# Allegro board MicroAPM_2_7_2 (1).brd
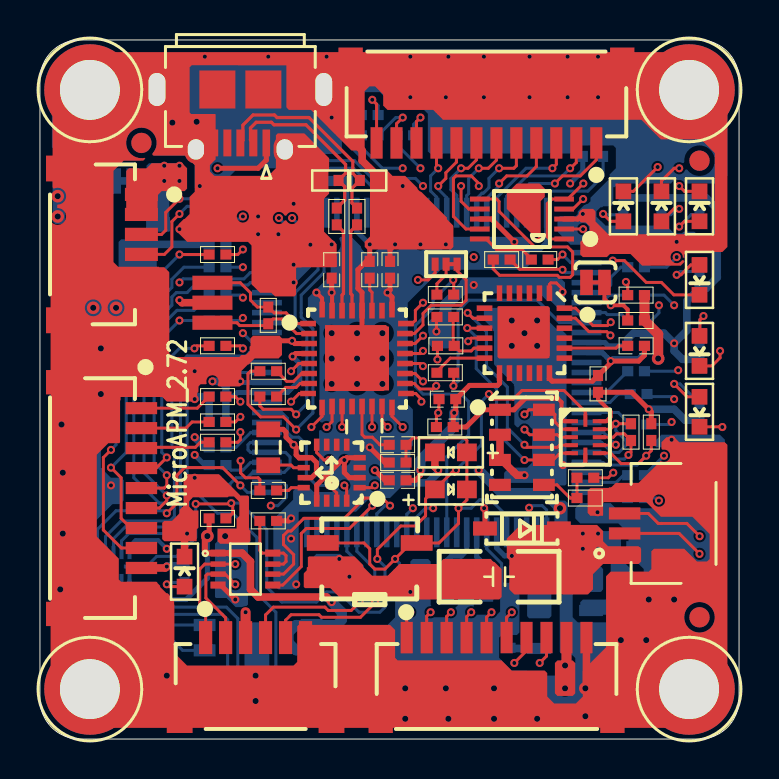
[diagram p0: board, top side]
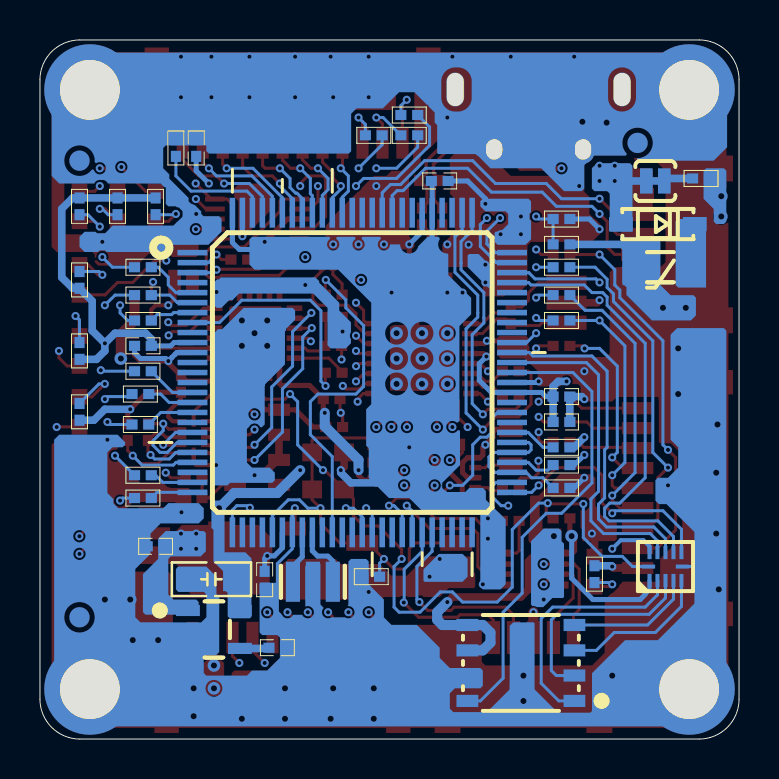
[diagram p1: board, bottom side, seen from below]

Outline 35 x 35 mm; copper layers: TOP, ART02, ART03, BOTTOM. Coordinates in mm from the lower left corner of the outline.
Outline path: 0,33 0,2 arc(0.59,0.59) 2,0 33,0 arc(34.41,0.59) 35,2 35,33 arc(34.41,34.41) 33,35 2,35 arc(0.59,34.41) 0,33

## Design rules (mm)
net group 3.3V: nets 3.3V SPI_OE
net group $$$14: nets $$$14 PH3
net group $$$15: nets $$$15 PE5
net group $$$16: nets $$$16 PE4
net group $$$17: nets $$$17 PE3
net group $$$19: nets $$$19 PH4
net group $$$20: nets $$$20 PH5
net group $$$21: nets $$$21 PB5
net group $$$22: nets $$$22 PB6
net group $$$23: nets $$$23 IN6
net group $$$24: nets $$$24 IN5
net group $$$25: nets $$$25 PPM_MISO
net group $$$26: nets $$$26 PPM_MOSI
net group $$$27: nets $$$27 PPM_SCK
net group $$$4718: nets $$$4718 PL1
net group $$$21225: nets $$$21225 PE1
net group $$$21228: nets $$$21228 PE0
net group $$$23578: nets $$$23578 PJ3
net group $$$25859: nets $$$25859 IN7
net group $$$25863: nets $$$25863 IN0
net group $$$27159: nets $$$27159 $$$27864
net group $$$27161: nets $$$27161 $$$27865
net group $$$27480: nets $$$27480 $$$27485
net group CH5: nets CH5 IN4
net group CS_MS5611: nets CS_MS5611 PG1
net group INT: nets INT PE6
net group PA1: nets PA1 PPM_PD0
net group PA2: nets PA2 PPM_PD1

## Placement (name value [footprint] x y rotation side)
C1  CAP0402-CAP  [C0402]  20.27 15.62 0 top
C2  CAP0402-CAP  [C0402]  8.89 15.88 180 bottom
C3  CAP0402-CAP  [C0402]  29.84 19.68 0 bottom
C4  CAP0402-CAP  [C0402]  17.91 12.95 180 top
C5  CAP0402-CAP  [C0402]  27.94 17.78 270 top
C6  CAP0402-CAP  [C0402]  14.99 27.94 180 bottom
C7  CAP0402-CAP  [C0402]  27.18 29.59 270 bottom
C8  CAP0402-CAP  [C0402]  11.43 12.45 0 top
C9  CAP0402-CAP  [C0402]  20.4 17.02 0 top
C10  CAP0805  [0805]  11.43 14.61 90 top
C11  CAP0402-CAP  [C0402]  23.11 4.57 0 bottom
C12  CAP1206  [C1206]  22.99 8.13 180 top
C13  CAP0402-CAP  [C0402]  29.84 19.68 180 top
C14  CAP0402-CAP  [C0402]  17.53 23.5 90 top
C15  CAP0402-CAP  [C0402]  17.91 14.73 0 top
C16  CAP0402-CAP  [C0402]  14.61 23.5 90 top
C17  CAP0402-CAP  [C0402]  16.51 23.5 90 top
C18  CAP0402-CAP  [C0402]  23.75 7.98 270 bottom
C19  CAP0402-CAP  [C0402]  8.89 17.14 180 bottom
C21  CAP0402-CAP  [C0402]  29.21 9.65 180 bottom
C22  CAP0805  [C0805]  26.42 8 270 bottom
D1  DIODESOD-123  [SOD-123]  4.06 25.78 0 bottom
D2  DIODE  [DIO-0603]  20.57 12.5 0 top
D3  DIODE  [DIO-0603]  20.57 14.35 180 top
D4  DIODESOD-123  [SOD-123]  24.13 10.54 180 top
F2  PTCSMD  [PTC-1206]  3.94 23.62 0 bottom
IC2  AT45DB161D-MU-NOPAD  [VDFN-8-NO-BOTTOM-PAD]  10.92 3.81 0 bottom
J1  CON6-SMD  [SD-53621-06]  5.08 24.77 270 top
J2  CON6-SMD  [SD-53621-06]  10.79 5.08 0 top
J3  CON4-SMD  [SD-53621-04]  33.15 10.79 90 top
J4  CON10-SMD  [SD-53621-10]  5.08 12.06 270 top
J5  CON10-SMD  [SD-53621-10]  22.86 5.08 0 top
J6  CON12-SMD  [SD-53621-12]  22.35 29.84 180 top
J18  MICRO_USB  [MOLEX_MICRO_USB_AB_BOTTOM_MOUNT]  10.03 29.84 0 top
LED1  LED  [LED-0603]  31.11 26.67 0 top
LED2  LED  [LED-0603]  29.21 26.67 0 top
LED3  LED  [LED-0603]  33.02 26.67 0 top
LED4  LED  [LED-0603]  33.02 16.38 180 top
LED5  LED  [LED-0603]  33.02 19.43 180 top
LED6  LED  [LED-0603]  7.24 8.38 0 top
LED7  LED  [LED-0603]  33.02 22.99 180 top
NOREF  #VAL  [unnamed]  33.02 6.1 0 top
NOREF#2  #VAL  [unnamed]  33.02 28.96 0 top
NOREF#3  -  [#2]  2 0 90 top
NOREF#4  -  [#2]  2.5 2.5 90 top
NOREF#5  #VAL  [unnamed]  32.5 2.5 0 top
NOREF#6  #VAL  [unnamed]  2.5 2.5 0 top
NOREF#7  -  [#2]  0 33.03 0 top
NOREF#8  -  [#2]  20.89 25.85 0 top
NOREF#9  #VAL  [unnamed]  2.5 32.5 0 top
NOREF#10  #VAL  [unnamed]  5.08 29.84 0 top
NOREF#11  -  [#2]  -99.11 -34.19 0 top
NOREF#12  #VAL  [unnamed]  32.5 32.5 0 top
NOREF#13  -  [#2]  2.5 32.5 0 top
NOREF#14  #VAL  [unnamed]  33.02 28.96 180 bottom
NOREF#15  #VAL  [unnamed]  33.02 6.1 180 bottom
NOREF#16  #VAL  [unnamed]  5.08 29.84 180 bottom
R1  RESISTOR0402-RES_2  [R0402]  29.84 23.62 180 bottom
R2  RESISTOR0402-RES_2  [R0402]  29.84 22.23 180 bottom
R3  RESISTOR0402-RES_2  [R0402]  29.84 20.95 180 bottom
R4  RESISTOR0402-RES_2  [R0402]  29.84 18.41 180 bottom
R5  RESISTOR0402-RES_2  [R0402]  29.97 17.27 180 bottom
R6  RESISTOR0402-RES_2  [R0402]  29.97 15.75 180 bottom
R7  RESISTOR0402-RES_2  [R0402]  29.84 13.21 180 bottom
R8  RESISTOR0402-RES_2  [R0402]  29.84 12.06 180 bottom
R9  RESISTOR0402-RES  [R0402]  29.84 22.23 0 top
R10  RESISTOR0402-RES_2  [R0402]  27.3 13.08 0 top
R11  RESISTOR0402-RES_2  [R0402]  20.29 22.25 180 top
R12  RESISTOR0402-RES  [R0402]  11.43 10.92 0 top
R13  RESISTOR0402-RES  [R0402]  31.11 26.67 90 bottom
R14  RESISTOR0402-RES_2  [R0402]  8.89 13.72 0 bottom
R15  RESISTOR0402-RES_2  [R0402]  8.89 12.57 0 bottom
R16  RESISTOR0402-RES  [R0402]  29.84 20.95 0 top
R17  RES  [R0402]  30.61 15.37 90 top
R18  RESISTOR0402-RES  [R0402]  29.21 26.67 90 bottom
R19  RESISTOR0402-RES_2  [R0402]  20.29 18.34 0 top
R20  RESISTOR0402-RES  [R0402]  33.02 26.67 90 bottom
R21  RES  [R0402]  29.59 15.37 270 top
R22  RESISTOR0402-RES_2  [R0402]  20.32 19.68 180 top
R23  RESISTOR0402-RES_2  [R0402]  20.29 21.13 180 top
R24  RES  [R0402]  18.41 8.13 0 bottom
R25  RESISTOR0402-RES_2  [R0402]  8.89 11.05 0 top
R26  RESISTOR0402-RES  [R0402]  17.91 13.84 180 top
R27  RESISTOR0402-RES_2  [R0402]  23.11 24 180 top
R28  RESISTOR0402-RES  [R0402]  28.19 29.59 270 bottom
R29  RESISTOR0402-RES_2  [R0402]  11.43 21.21 90 top
R30  RESISTOR0402-RES_2  [R0402]  25.02 24 180 top
R31  RESISTOR0402-RES_2  [R0402]  14.86 26.16 90 top
R32  RESISTOR0402-RES_2  [R0402]  33.02 16.38 90 bottom
R33  RESISTOR0402-RES_2  [R0402]  27.3 12.06 0 top
R34  RESISTOR0402-RES_2  [R0402]  15.88 26.16 90 top
R35  RESISTOR0402-RES_2  [R0402]  33.02 19.43 90 bottom
R36  RESISTOR0402-RES  [R0402]  7.24 8.26 90 bottom
R37  RESISTOR0402-RES  [R0402]  8.89 24.77 180 bottom
R38  RESISTOR0402-RES_2  [R0402]  8.89 24.26 0 top
R39  RESISTOR0402-RES_2  [R0402]  8.89 23.62 0 bottom
R40  RESISTOR0402-RES_2  [R0402]  8.89 22.23 0 bottom
R41  RESISTOR0402-RES_2  [R0402]  8.89 20.95 0 bottom
R42  RESISTOR0402-RES_2  [R0402]  8.89 19.68 0 top
R43  RESISTOR0402-RES_2  [R0402]  8.89 14.86 0 top
R44  RESISTOR0402-RES_2  [R0402]  8.89 15.88 0 top
R45  RESISTOR0402-RES_2  [R0402]  8.89 17.14 0 top
R46  RESISTOR0402-RES_2  [R0402]  11.43 17.14 0 top
R47  RESISTOR0402-RES_2  [R0402]  11.43 18.41 0 top
R48  RESISTOR0402-RES  [R0402]  8.89 14.61 180 bottom
R49  RESISTOR0402-RES_2  [R0402]  1.91 28.07 180 bottom
R50  RESISTOR0402-RES_2  [R0402]  18.29 30.23 180 bottom
R51  RESISTOR0402-RES_2  [R0402]  33.02 22.99 90 bottom
R52  RESISTOR0402-RES_2  [R0402]  16.51 30.23 180 bottom
R53  RESISTOR0402-RES_2  [R0402]  16.51 31.24 180 bottom
R54  RES  [R0402]  8.89 26.04 180 bottom
SJ1  SOLDERJUMPERNO  [SJ_2S-NO]  4.19 27.94 180 bottom
SJ4  JUMP3P  [JUMP3]  20.33 23.77 0 top
SJ10  SOLDERJUMPERNO  [SJ_2S-NO]  27.81 22.86 0 top
SW1  PTS044  [PTS-044]  16.51 9.02 180 top
U1  ATMEGA1280-16AU  [TQFP100]  19.37 18.35 180 bottom
U2  PCA9306DC  [VSSOP8]  10.29 8.51 0 top
U3  V_REG_LDOSMD  [SOT23-5]  26.29 5.49 270 bottom
U5  MPU-3000  [QFN-24]  24.26 20.32 270 top
U7  TS5A23157  [MSOP10]  24.13 26.04 90 top
U8  ATMEGA32U2-MU  [ATMEL_QFN32]  15.88 19.05 0 top
U12  -  [MS5611-01BA]  24.13 14.61 0 top
U13  HMC5883L  [LPCC16]  14.61 13.34 180 top
U_14  TXB0104UQFN  [UQFN-12]  27.3 15.11 270 top
U_15  TXB0104UQFN  [UQFN-12]  3.68 8.64 180 bottom
Y1  CSTCT16M0V53  [RESONATOR]  8.64 21.84 270 top
Y2  CSTCT16M0V53  [RESONATOR]  21.34 7.87 0 bottom
Z1  VARISTORCN0603  [FB-0402]  16.43 27.97 0 top
Z2  VARISTORCN0603  [FB-0402]  14.53 27.97 180 top

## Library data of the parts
C1-C9 C11 C13-C19 C21 = C0402: Tolerance: #TOL; User Part Number: HAMP
C10 = 0805: Tolerance: #TOL; User Part Number: HAMP
C12 = C1206: Tolerance: #TOL; User Part Number: HAMP
C22 = C0805: Tolerance: #TOL; User Part Number: HAMP
D1 D4 = SOD-123: Tolerance: #TOL; User Part Number: HAMP
D2 D3 = DIO-0603: Tolerance: #TOL; User Part Number: HAMP
F2 = PTC-1206: Tolerance: #TOL; User Part Number: HAMP
IC2 = VDFN-8-NO-BOTTOM-PAD: Tolerance: #TOL; User Part Number: HAMP
J1 J2 = SD-53621-06: Tolerance: #TOL; User Part Number: HAMP
J3 = SD-53621-04: Tolerance: #TOL; User Part Number: HAMP
J4 J5 = SD-53621-10: Tolerance: #TOL; User Part Number: HAMP
J6 = SD-53621-12: Tolerance: #TOL; User Part Number: HAMP
J18 = MOLEX_MICRO_USB_AB_BOTTOM_MOUNT: Tolerance: #TOL; User Part Number: HAMP
LED1-LED7 = LED-0603: Tolerance: #TOL; User Part Number: HAMP
NOREF NOREF#2 NOREF#5 NOREF#6 NOREF#9 NOREF#10 NOREF#12 NOREF#14-NOREF#16 = -: Tolerance: #TOL; User Part Number: HAMP
R1-R8 R10 R11 R14 R15 R19 R22 R23 R25 R27 R29-R35 R38-R47 R51 = R0402: Tolerance: #TOL; User Part Number: HAMP; signal model: R0402_RESISTOR0402-RES_2
R9 R12 R13 R16-R18 R20 R21 R24 R26 R28 R36 R37 R48-R50 R52-R54 = R0402: Tolerance: #TOL; User Part Number: HAMP
SJ1 SJ10 = SJ_2S-NO: Tolerance: #TOL; User Part Number: HAMP
SJ4 = JUMP3: Tolerance: #TOL; User Part Number: HAMP
SW1 = PTS-044: Tolerance: #TOL; User Part Number: HAMP
U1 = TQFP100: Tolerance: #TOL; User Part Number: HAMP
U2 = VSSOP8: Tolerance: #TOL; User Part Number: HAMP
U3 = SOT23-5: Tolerance: #TOL; User Part Number: HAMP
U5 = QFN-24: Tolerance: #TOL; User Part Number: HAMP
U7 = MSOP10: Tolerance: #TOL; User Part Number: HAMP
U8 = ATMEL_QFN32: Tolerance: #TOL; User Part Number: HAMP
U12 = MS5611-01BA: Tolerance: #TOL; User Part Number: HAMP
U13 = LPCC16: Tolerance: #TOL; User Part Number: HAMP
U_14 U_15 = UQFN-12: Tolerance: #TOL; User Part Number: HAMP
Y1 Y2 = RESONATOR: Tolerance: #TOL; User Part Number: HAMP
Z1 Z2 = FB-0402: Tolerance: #TOL; User Part Number: HAMP

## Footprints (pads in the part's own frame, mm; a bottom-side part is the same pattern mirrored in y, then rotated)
0805
  rect 0.787x1.194 smd: 1(-0.9,0) 2(0.9,0)
ATMEL_QFN32
  rect 0.787x0.279 smd: 1(-2.45,1.75) 2(-2.4,1.25) 3(-2.4,0.75) 4(-2.4,0.25) 5(-2.4,-0.25) 6(-2.4,-0.75) 7(-2.4,-1.25) 8(-2.45,-1.75) 17(2.45,-1.75) 18(2.4,-1.25) 19(2.4,-0.75) 20(2.4,-0.25) 21(2.4,0.25) 22(2.4,0.75) 23(2.4,1.25) 24(2.45,1.75)
  rect 0.279x0.787 smd: 9(-1.75,-2.45) 10(-1.25,-2.4) 11(-0.75,-2.4) 12(-0.25,-2.4) 13(0.25,-2.4) 14(0.75,-2.4) 15(1.25,-2.4) 16(1.75,-2.45) 25(1.75,2.45) 26(1.25,2.4) 27(0.75,2.4) 28(0.25,2.4) 29(-0.25,2.4) 30(-0.75,2.4) 31(-1.25,2.4) 32(-1.75,2.45)
  rect 3.2x3.2 smd: 33(0,0)
C0402
  rect 0.559x0.508 smd: 1(-0.42,0) 2(0.42,0)
C0805
  rect 1.194x1.092 smd: 1(0,1.13) 2(0,-1.17)
C1206
  rect 1.524x1.524 smd: 1(-1.71,0) 2(1.71,0)
DIO-0603
  rect 0.991x0.889 smd: 1(0.8,0) 2(-0.8,0)
FB-0402
  rect 0.508x0.559 smd: 1(-0.42,0) 2(0.42,0)
JUMP3
  rect 0.356x0.66 smd: 1(-0.55,0) 2(0.55,0) 3(0,0)
LED-0603
  rect 0.787x0.787 smd: 1(0,0.75) 2(0,-0.75)
LPCC16
  rect 0.61x0.279 smd: 1(-1.4,0.75) 2(-1.4,0.25) 3(-1.4,-0.25) 4(-1.4,-0.75) 9(1.4,-0.75) 10(1.4,-0.25) 11(1.4,0.25) 12(1.4,0.75)
  rect 0.279x0.61 smd: 5(-0.75,-1.4) 6(-0.25,-1.4) 7(0.25,-1.4) 8(0.75,-1.4) 13(0.75,1.4) 14(0.25,1.4) 15(-0.25,1.4) 16(-0.75,1.4)
MOLEX_MICRO_USB_AB_BOTTOM_MOUNT
  oval 0.889x1.702 hole 0.838x1.651: (-4.175,2.675) (4.175,2.675)
  rect 0.381x1.346 smd: 1(1.3,0) 5(-1.3,0)
  rect 0.406x1.346 smd: 2(0.65,0) 3(0,0) 4(-0.65,0)
  oval 1.118x1.422 hole 0.813x1.016: 6(2.225,-0.325) 7(-2.225,-0.325)
  custom 0.475x0.475 smd: 8(-3.663,2.675) 9(3.663,2.675)
  rect 1.803x1.905 smd: 10(-1.15,2.675) 11(1.15,2.675)
MS5611-01BA
  rect 1.092x0.61 smd: 1(-1.1,1.88) 2(-1.1,0.63) 3(-1.1,-0.63) 4(-1.1,-1.88) 5(1.1,-1.88) 6(1.1,-0.63) 7(1.1,0.63) 8(1.1,1.88)
MSOP10
  rect 0.254x0.991 smd: 1(-1,-2.11) 2(-0.5,-2.11) 3(0,-2.11) 4(0.5,-2.11) 5(1,-2.11) 6(1,2.11) 7(0.5,2.11) 8(0,2.11) 9(-0.5,2.11) 10(-1,2.11)
PTC-1206
  rect 0.991x1.803 smd: 1(-1.4,0) 2(1.4,0)
PTS-044
  rect 1.6x0.787 smd: 1(-2.35,0.8) 2(2.35,0.8) 3(2.35,-0.8) 4(-2.35,-0.8)
QFN-24
  rect 0.787x0.279 smd: 1(-2,1.25) 2(-2,0.75) 3(-2,0.25) 4(-2,-0.25) 5(-2,-0.75) 6(-2,-1.25) 13(2,-1.25) 14(2,-0.75) 15(2,-0.25) 16(2,0.25) 17(2,0.75) 18(2,1.25)
  rect 0.279x0.787 smd: 7(-1.25,-2) 8(-0.75,-2) 9(-0.25,-2) 10(0.25,-2) 11(0.75,-2) 12(1.25,-2) 19(1.25,2) 20(0.75,2) 21(0.25,2) 22(-0.25,2) 23(-0.75,2) 24(-1.25,2)
  rect 2.489x2.489 smd: 25(0,0)
R0402
  rect 0.559x0.508 smd: 1(-0.42,0) 2(0.42,0)
RESONATOR
  rect 0.711x2.007 smd: 1(-1,0) 2(1,0) 3(0,0)
SD-53621-04
  rect 0.61x1.575 smd: 1(-1.5,3.875) 2(-0.5,3.875) 3(0.5,3.875) 4(1.5,3.875)
  rect 1.194x1.803 smd: 5(-2.8,0) 6(2.8,0)
SD-53621-06
  rect 0.66x1.651 smd: 1(-2.5,0) 2(-1.5,0) 3(-0.5,0) 4(0.5,0) 5(1.5,0) 6(2.5,0)
  rect 1.295x1.803 smd: 7(-3.8,-3.875) 8(3.8,-3.875)
SD-53621-10
  rect 0.61x1.575 smd: 1(-4.5,0) 2(-3.5,0) 3(-2.5,0) 4(-1.5,0) 5(-0.5,0) 6(0.5,0) 7(1.5,0) 8(2.5,0) 9(3.5,0) 10(4.5,0)
  rect 1.219x1.803 smd: 11(-5.8,-3.875) 12(5.8,-3.875)
SD-53621-12
  rect 0.61x1.575 smd: 1(-5.5,0) 2(-4.5,0) 3(-3.5,0) 4(-2.5,0) 5(-1.5,0) 6(-0.5,0) 7(0.5,0) 8(1.5,0) 9(2.5,0) 10(3.5,0) 11(4.5,0) 12(5.5,0)
  rect 1.219x1.803 smd: 13(-6.8,-3.875) 14(6.8,-3.875)
SJ_2S-NO
  rect 0.635x1.27 smd: 1(-0.45,0) 2(0.45,0)
SOD-123
  rect 1.194x0.711 smd: 1(1.85,0) 2(-1.85,0)
SOT23-5
  rect 0.559x1.194 smd: 1(-0.95,-1.3) 2(0,-1.3) 3(0.95,-1.3) 4(0.95,1.3) 5(-0.95,1.3)
TQFP100
  rect 1.499x0.279 smd: 1(-8,6) 2(-8,5.5) 3(-8,5) 4(-8,4.5) 5(-8,4) 6(-8,3.5) 7(-8,3) 8(-8,2.5) 9(-8,2) 10(-8,1.5) 11(-8,1) 12(-8,0.5) 13(-8,0) 14(-8,-0.5) 15(-8,-1) 16(-8,-1.5) 17(-8,-2) 18(-8,-2.5) 19(-8,-3) 20(-8,-3.5) 21(-8,-4) 22(-8,-4.5) 23(-8,-5) 24(-8,-5.5) 25(-8,-6) 51(8,-6) 52(8,-5.5) 53(8,-5) 54(8,-4.5) 55(8,-4) 56(8,-3.5) 57(8,-3) 58(8,-2.5) 59(8,-2) 60(8,-1.5) 61(8,-1) 62(8,-0.5) 63(8,0) 64(8,0.5) 65(8,1) 66(8,1.5) 67(8,2) 68(8,2.5) 69(8,3) 70(8,3.5) 71(8,4) 72(8,4.5) 73(8,5) 74(8,5.5) 75(8,6)
  rect 0.279x1.499 smd: 26(-6,-8) 27(-5.5,-8) 28(-5,-8) 29(-4.5,-8) 30(-4,-8) 31(-3.5,-8) 32(-3,-8) 33(-2.5,-8) 34(-2,-8) 35(-1.5,-8) 36(-1,-8) 37(-0.5,-8) 38(0,-8) 39(0.5,-8) 40(1,-8) 41(1.5,-8) 42(2,-8) 43(2.5,-8) 44(3,-8) 45(3.5,-8) 46(4,-8) 47(4.5,-8) 48(5,-8) 49(5.5,-8) 50(6,-8) 76(6,8) 77(5.5,8) 78(5,8) 79(4.5,8) 80(4,8) 81(3.5,8) 82(3,8) 83(2.5,8) 84(2,8) 85(1.5,8) 86(1,8) 87(0.5,8) 88(0,8) 89(-0.5,8) 90(-1,8) 91(-1.5,8) 92(-2,8) 93(-2.5,8) 94(-3,8) 95(-3.5,8) 96(-4,8) 97(-4.5,8) 98(-5,8) 99(-5.5,8) 100(-6,8)
unnamed
  round 1.016 smd: 1(0,0)
UQFN-12
  rect 0.203x0.66 smd: 1(-0.8,-0.7) 2(-0.4,-0.7) 3(0,-0.7) 4(0.4,-0.7) 5(0.8,-0.7) 7(0.8,0.7) 8(0.4,0.7) 9(0,0.7) 10(-0.4,0.7) 11(-0.8,0.7)
  rect 0.66x0.203 smd: 6(0.85,0) 12(-0.85,0)
VDFN-8-NO-BOTTOM-PAD
  rect 1.092x0.61 smd: 1(-2.68,1.9) 2(-2.68,0.63) 3(-2.68,-0.63) 4(-2.68,-1.9) 5(2.68,-1.9) 6(2.68,-0.63) 7(2.68,0.63) 8(2.68,1.9)
VSSOP8
  rect 0.762x0.356 smd: 1(-1.37,0.8) 4(-1.37,-0.8) 5(1.37,-0.8) 8(1.37,0.8)
  rect 0.762x0.279 smd: 2(-1.37,0.25) 3(-1.37,-0.25) 6(1.37,-0.25) 7(1.37,0.25)

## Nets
3.3V: C1.2 C4.1 C9.2 C22.1 IC2.5 IC2.6 R9.2 R16.2 R25.1 U2.1 U3.5 U5.13 U12.1 U13.2 U13.4 U13.13 U_14.1 U_15.1
5V: J5.9 R49.2
GND: C1.1 C2.2 C3.2 C4.2 C5.1 C6.2 C7.1 C9.1 C10.2 C11.1 C12.2 C13.1 C14.2 C16.2 C17.2 C18.2 C19.2 C21.1 C22.2 D4.1 IC2.7 J1.5 J1.6 J1.7 J1.8 J2.6 J2.7 J2.8 J3.4 J3.5 J3.6 J4.10 J4.11 J4.12 J5.10 J5.11 J5.12 J6.13 J6.14 J18.5 J18.6 J18.7 J18.8 J18.9 LED6.1 R15.1 R23.2 R24.2 R28.1 R33.2 R48.2 R54.2 SW1.1 SW1.2 U1.11 U1.32 U1.62 U1.81 U1.99 U2.4 U3.2 U3.3 U5.1 U5.18 U7.3 U8.3 U8.28 U8.33 U12.2 U12.3 U13.9 U13.11 U_14.6 U_15.6 Y1.3 Y2.3 Z1.2 Z2.2
VCC: C2.1 C3.1 C5.2 C6.1 C12.1 C14.1 C16.1 C18.1 C19.1 C21.2 D3.1 D4.2 F2.2 J2.3 J3.1 J4.9 J18.1 R12.2 R13.2 R14.1 R17.2 R18.2 R20.2 R26.2 R32.1 R35.1 R36.2 R37.2 R51.1 U1.10 U1.31 U1.61 U1.80 U1.100 U3.1 U7.8 U8.4 U8.25 U8.31 U8.32 U_14.11 U_15.11
3DR_RX: J3.3 U7.9
3DR_TX: J3.2 U7.7
#RST: C15.1 U8.13
$$$7: LED6.2 R36.1
$$$8: C13.2 U5.20
$$$9: C7.2 U5.10
$$$11: D1.2 F2.1
$$$12: C11.2 U3.4
$$$13: C10.1 U13.10
$$$14: J5.5 R4.1
$$$15: J5.6 R3.1
$$$16: J5.7 R2.1
$$$17: J5.8 R1.1
$$$18: R12.1 U2.7 U2.8
$$$19: J5.4 R5.1
$$$20: J5.3 R6.1
$$$21: J5.2 R7.1
$$$22: J5.1 R8.1
$$$23: J4.7 R39.1
$$$24: J4.6 R40.1
$$$25: J4.4 R42.1
$$$26: J4.3 R43.1
$$$27: J4.2 R44.1
$$$29: C8.1 U13.8
$$$30: C8.2 U13.12
$$$31: LED1.2 R13.1
$$$32: LED2.2 R18.1
$$$33: LED3.2 R20.1
$$$34: U1.34 Y2.1
$$$35: U1.33 Y2.2
$$$4718: R11.2 SJ4.3
$$$21225: R27.2 U7.6
$$$21228: R30.2 U7.10
$$$23578: R22.1 R23.1 U5.11
$$$25859: J4.8 R38.1
$$$25863: J4.1 R45.1
$$$27159: J18.2 R31.2 Z2.1
$$$27161: J18.3 R34.2 Z1.1
$$$27480: R29.1 U8.2 Y1.2
$$$27485: R29.2 U8.1 Y1.1
$$$27841: C17.1 U8.27
$$$27864: R31.1 U8.30
$$$27865: R34.1 U8.29
$$$30141: R28.2 U1.98
$$$32146: J6.10 R50.1
$$$32167: J6.11 R52.1
$$$32195: J6.12 R53.1
CH5: J4.5 R41.1 SJ4.1
CS_DF: IC2.4 U_15.4
CS_MS5611: R10.1 R33.1 U12.5
HI: R14.2 U1.54
IN0: R45.2 U8.14
IN4: R41.2 U8.18
IN5: R40.2 U8.19
IN6: R39.2 U8.20
IN7: R38.2 U8.21
INT: R19.1 U5.12
JP_VCC: D1.1 J1.1 J1.2 R49.1 SJ1.1 SJ1.2
LO: R15.2 U1.53 U1.55 U1.56
MISO_3V3: U5.9 U12.6 U_14.5
MOSI_3V3: U5.24 U12.7 U_14.3
MOSI_DF: IC2.1 U_15.2
NET_R32_2: LED4.2 R32.2
NET_R35_2: LED5.2 R35.2
NET_R51_2: LED7.2 R51.2
PA1: R47.1 U1.77
PA2: R46.1 U1.76
PA3: LED3.1 U1.75
PA4: LED2.1 U1.74
PA5: LED1.1 U1.73
PA6: U1.72 U_15.8
PB0: U1.19 U_14.8
PB1: R21.1 U1.20 U_14.10
PB2: R21.2 U1.21 U_14.9
PB3: R17.1 U1.22 U_14.7
PB5: R7.2 U1.24
PB6: R8.2 U1.25
PB7: R50.2 U1.26
PC4: R48.1 U1.57
PC6: U1.59 U13.15
PC7_LED: LED7.1 U8.22
PD0: U1.43 U2.6
PD1: U1.44 U2.5
PD2: J2.5 U1.45
PD3: J2.4 U1.46
PE0: R30.1 U1.2
PE1: R27.1 U1.3
PE3: R1.2 U1.5
PE4: R2.2 U1.6
PE5: R3.2 U1.7
PE6: R19.2 U1.8
PF0: J6.1 U1.97
PF1: J6.2 U1.96
PF2: J6.3 U1.95
PF3: J6.4 U1.94
PF4: J6.5 U1.93
PF5: J6.6 U1.92
PF6: J6.7 U1.91
PF7: J6.8 U1.90
PG0: U1.51 U_15.7
PG1: R10.2 U1.52
PH3: R4.2 U1.15
PH4: R5.2 U1.16
PH5: R6.2 U1.17
PJ0: IC2.8 U1.63
PJ1: U1.64 U_15.10
PJ2: U1.65 U_15.9
PJ3: R22.2 U1.66
PK0: J6.9 U1.89
PK4: J1.3 U1.85
PK5: J1.4 U1.84
PL1: R11.1 U1.36
PL4: R52.2 U1.39
PL5: R53.2 U1.40
PPM_MISO: R42.2 U8.17
PPM_MOSI: R43.2 U8.16
PPM_OUT: SJ4.2 U8.23
PPM_PC2: U7.1 U7.5 U8.5
PPM_PD0: R47.2 U8.6
PPM_PD1: R46.2 U8.7
PPM_RST: R37.1 R54.1 U8.24
PPM_RX: U7.4 U8.8
PPM_SCK: R44.2 U8.15
PPM_TX: U7.2 U8.9
RST: C15.2 D2.1 D3.2 R24.1 R26.1 SW1.3 SW1.4 U1.30
RST_DF: IC2.3 U_15.5
RXLED: LED4.1 U8.10
SCK_3V3: U5.23 U12.8 U_14.2
SCK_DF: IC2.2 U_15.3
SCL1: J2.1 R9.1 U2.2 U13.1
SDA1: J2.2 R16.1 SJ10.1 SJ10.2 U2.3 U13.16
SPI_OE: D2.2 R25.2 U_14.12 U_15.12
SS_3V3: U5.8 U_14.4
TXLED: LED5.1 U8.11

Pads without a net: J18 4 10 11; NOREF 1; NOREF#2 1; NOREF#5 1; NOREF#6 1; NOREF#9 1; NOREF#10 1; NOREF#12 1; NOREF#14 1; NOREF#15 1; NOREF#16 1; U1 1 4 9 12 13 14 18 23 27 28 29 35 37 38 41 42 47 48 49 50 58 60 67 68 69 70 71 78 79 82 83 86 87 88; U5 2 3 4 5 6 7 14 15 16 17 19 21 22 25; U8 12 26; U12 4; U13 3 5 6 7 14

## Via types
v1: diameter 0.406, hole 0.203, TOP to BOTTOM, 230 vias
v2: diameter 0.635, hole 0.305, TOP to BOTTOM, 48 vias

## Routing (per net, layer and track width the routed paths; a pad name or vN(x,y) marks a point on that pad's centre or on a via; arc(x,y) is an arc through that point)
3.3V: length 79.5
  TOP w0.203: 25.91,17.07 26.11,16.87 26.11,16.05 26.25,15.91 U_14.1
  TOP w0.254: 25.91,17.07 24.31,17.07 23.72,16.49 U12.1 22.2,16.49 21.34,15.62 C1.2 20.69,16.28 v1(20.74,16.33) 20.82,16.41 C9.2 21.5,17.7 22.91,17.7 23.01,17.8 U5.13 ; v2(8.38,10.16) 8.47,10.25 R25.1 ; U13.4 15.36,14.09 v1(15.24,13.97) ; v1(19.05,13.46) 19.05,13.21 18.8,12.95 C4.1 ; U13.2 15.49,13.08 15.24,13.34 v1(15.24,13.97) ; v1(15.24,13.97) 15.11,13.97 13.85,12.71 U13.13
  TOP w0.305: v2(8.38,10.16) 8.26,10.03 8.26,9.44 8.38,9.31 9.53,9.31
  TOP w0.381: v1(14.61,6.86) 14.35,7.11 10.92,7.11 10.54,7.49 10.54,8.89 10.12,9.31 9.53,9.31
  TOP w0.508: v2(30.95,19.05) 30.95,20.27 R16.2 R9.2
  ART03 w0.508: v2(8.38,10.16) 8.38,10.41 9.02,11.05 9.02,11.58 9.02,12.7 9.65,13.34 14.76,13.34 15.24,13.82 v1(15.24,13.97) 15.29,14.02 18.49,14.02 v1(19.05,13.46) 19.68,14.1 21.34,14.1 v1(21.97,13.46) ; v2(30.95,19.05) 30.89,19.05 27.69,15.85 27.69,13.21 v2(26.04,11.56)
  BOTTOM w0.203: 4.7,7.24 4.48,7.46 U_15.1
  BOTTOM w0.254: v2(8.38,10.16) 8.38,8.05 7.32,6.99 4.95,6.99 4.7,7.24
  BOTTOM w0.508: v2(26.04,11.56) 25.27,12.32 23.11,12.32 v1(21.97,13.46) ; v1(19.05,13.46) 19.05,13.97 20.74,15.66 v1(20.74,16.33) ; v1(14.61,6.86) 15.11,6.35 15.11,5.97 14.85,5.71 IC2.5 12.83,5.71 12.45,5.33 12.45,4.83 12.83,4.44 IC2.6
5V: length 1.4
  TOP w0.508: J5.9 26.36,3.75 v2(26.29,3.68)
  vias: v2(0.89,27.18) v2(0.89,26.16) v2(26.29,2.54)
GND: length 59
  TOP w0.152: v1(26.16,22.38) 26.16,22.53 25.85,22.83 25.58,22.83 25.51,22.76 U5.1 ; R23.2 19.85,21.11 v1(19.85,20.4) ; C1.1 19.85,16.24 v1(19.94,16.33) 19.98,16.37 C9.1
  TOP w0.203: v1(26.18,13.72) 27.18,13.72 27.3,13.84 U_14.6
  TOP w0.254: C10.2 12.18,15.5 12.32,15.37 12.32,15.11 v1(12.7,14.73) 12.83,14.61 12.83,14.22 12.97,14.09 U13.9 13.6,14.09 13.84,13.84 13.84,13.34 13.59,13.08 U13.11 ; C13.1 30.26,19.22 29.97,18.92 v1(28.57,18.92) 28.57,18.83 C5.1 27.66,17.92 25.64,17.92 25.51,18.05 U5.18 ; v2(15.88,20.32) 16.13,20.57 U8.28 16.13,22.36 15.92,22.56 15.92,23.5 16.34,23.91 C17.2 v1(16.51,24.77) ; 11.81,19.94 v1(12.62,19.94) 12.76,19.8 U8.3 ; U7.3 26.92,26.04 v1(27.18,26.29) ; C4.2 17.27,12.95 v1(16.76,13.46) ; 8.92,7.71 9.05,7.71 v1(9.78,6.99) ; D4.1 22.28,11.52 v1(22.24,11.56) ; C14.2 17.53,24.51 v1(17.78,24.77)
  TOP w0.381: Z1.2 16.85,28.23 16.13,28.96 16.13,29.46 16,29.59 ; v1(6.99,21.97) 7.11,21.84 Y1.3 ; v1(24.26,13.21) 23.88,13.21 23.72,13.37 23.71,13.37 23.11,13.98 U12.3 U12.2 ; v2(27.3,2.54) 27.36,2.59 J5.10 ; LED6.1 7.24,10.16 v1(7.37,10.29)
  BOTTOM w0.152: 23.11,7.75 23.11,8.78 22.37,9.53 U1.32 ; U_15.6 2.18,8.64
  BOTTOM w0.203: U1.32 22.37,11.43 v1(22.24,11.56)
  BOTTOM w0.254: R54.2 7.49,26.04 v1(6.99,25.53) ; C13.1 30.26,19.34 29.97,19.05 28.7,19.05 v1(28.57,18.92) 28.39,19.1 28.39,19.11 28.23,19.27 28.23,19.27 28.15,19.35 U1.11 ; U1.81 15.87,25.41 v1(16.51,24.77) ; U1.99 v1(24.86,25.17) ; R15.1 8.26,12.57 v1(7.75,13.08) ; v1(10.03,17.91) 10.09,17.85 U1.62 ; v1(12.7,26.8) 12.7,27.05 13.59,27.94 C6.2
  BOTTOM w0.381: C2.2 C19.2 7.87,17.14 v1(7.75,17.02) ; R48.2 8.26,14.61 v1(7.75,15.11)
  vias: v1(3.56,12.7) v1(7.75,18.41) v1(8,27.69) v1(8.26,34.16) v1(10.92,26.16) v1(10.92,25.27) v1(11.43,34.16) v1(11.94,25.27) v1(12.7,23.75) v1(12.7,22.86) v1(13.54,24.75) v1(14.35,34.16) v1(14.61,31.11) v1(14.61,24.77) v1(14.99,9.02) v1(15.49,8.13) v1(18.16,27.69) v1(18.54,34.16) v1(18.54,32.13) v1(18.54,7.37) v1(19.05,24.77) v1(20.32,32.13) v1(20.32,24.77) v1(20.45,34.16) v1(21.72,24.13) v1(21.72,22.73) v1(22.23,34.16) v1(22.23,32.13) v1(24.51,34.16) v1(24.51,32.13) v1(26.42,34.16) v1(26.42,32.13) v1(27.94,34.16) v1(27.94,32.13) v1(27.91,11.35) v1(31.62,14.99) v1(31.88,24.89) v2(1.02,7.49) v2(1.08,15.75) v2(1.14,13.34) v2(1.14,10.29) v2(3.05,19.56) v2(3.05,17.27) v2(6.35,3.17) v2(6.63,30.86) v2(7.84,30.9) v2(9.27,10.16) v2(10.79,3.17) v2(10.79,1.91) v2(14.61,20.32) v2(14.61,19.05) v2(14.61,17.78) v2(15.88,19.05) v2(15.88,17.78) v2(17.14,20.32) v2(17.14,19.05) v2(17.14,17.78) v2(18.29,2.54) v2(18.29,1.02) v2(20.32,2.54) v2(20.45,1.02) v2(22.73,2.54) v2(22.73,1.02) v2(23.62,20.95) v2(23.62,19.68) v2(24.26,20.32) v2(24.89,20.95) v2(24.89,19.68) v2(24.89,1.02) v2(27.3,1.14) v2(29.08,4.95) v2(30.35,4.95) v2(30.48,6.99) v2(31.75,6.99)
VCC: length 82.9
  TOP w0.203: C5.2 27.94,17.02 28.57,16.38 28.57,16.13 28.36,15.91 U_14.11 ; v1(14.61,22.35) 14.62,22.33 U8.31 ; v1(13.84,22.35) 14.12,22.07 U8.32
  TOP w0.254: v1(14.61,22.35) C16.1 ; v1(12.57,11.05) 12.45,10.92 R12.2 ; R17.2 30.61,16.38 v1(30.48,16.51) 29.63,17.36 C5.2 ; v1(12.65,19.15) 12.8,19.3 U8.4 ; R26.2 17.27,13.84 v1(16.51,14.61) ; U7.8 22.61,26.04 v1(23.75,24.89) ; v1(8.89,28.57) 10.92,28.57 11.33,28.99 J18.1 ; U8.25 17.63,22.13 v1(17.4,22.35) 17.53,22.48 C14.1
  TOP w0.381: D3.1 19.77,13.63 v1(19.94,13.46) ; J4.9 6.28,8.57 v1(6.35,8.64)
  TOP w0.508: J2.3 v1(10.3,6.35)
  ART03 w0.254: 8.39,14.36 11.42,14.36 11.61,14.17 14.05,14.17 14.48,14.61 v1(16.51,14.61)
  ART03 w0.381: v1(31.75,19.81) 31.62,19.68 31.62,18.86 31.05,18.29 31.05,17.08
  BOTTOM w0.203: U_15.11 4.48,9.65 4.79,9.96 5.92,9.96 v1(6.35,9.53)
  BOTTOM w0.254: C18.1 23.75,9.04 v1(23.62,9.17) 23.26,9.17 22.87,9.57 U1.31 ; U1.10 28.28,19.85 28.45,19.68 C3.1 ; C6.1 15.37,27.9 U1.80 15.37,24.89 15.37,24.89 ; C19.1 9.68,17.14 9.88,17.35 U1.61 12.4,17.35 13,17.96 13,18.8 v1(12.65,19.15) ; R14.1 8.26,13.72 v1(7.75,14.22) ; 24.38,24.51 25.02,24.51 25.36,24.86 U1.100
  BOTTOM w0.381: R32.1 32.3,15.96 31.75,16.51 v1(30.48,16.51) ; R35.1 32.17,19.01 31.75,19.43 v1(31.75,19.81) ; F2.2 5.34,24.26 5.84,24.77 R37.2 ; v1(19.94,13.46) 19.94,13.34 19.43,12.83 18.16,12.83 18.03,12.95 ; v1(6.35,8.64) 6.39,8.67 R36.2 ; C3.1 29.43,20.03 29.72,20.32 31.24,20.32 v1(31.75,19.81) ; v1(8.64,17.91) 9.06,17.91 9.31,17.65 C19.1 C2.1 ; v1(31.75,19.81) 32.38,20.45 32.38,21.93 R51.1 33.36,22.57 33.91,23.11 33.91,26.54 33.36,27.09 R20.2 R13.2 R18.2
  vias: v1(12.57,10.03) v1(12.83,7.75) v1(27.18,10.29) v1(27.18,9.53) v1(27.94,10.29) v1(27.94,9.53) v2(2.67,21.59) v2(3.81,21.59)
3DR_RX: length 39.4
  TOP w0.152: v1(21.97,27.69) 21.97,27.81 21.59,28.19 20.83,28.19 20.7,28.07 20.7,26.16 21.33,25.54 U7.9 ; v1(33.03,10.15) 32.38,10.79 30.95,10.8 30.45,11.29 J3.3
  ART03 w0.127: v1(33.03,10.15) 33.43,10.55 33.43,18.74 33.12,19.05 33.12,19.82 33.12,20.25 32.52,20.84 32.52,26.66 32.27,26.91 31,26.91 28.04,29.87 24.54,29.87 23.5,28.83 23.5,28.32 23.36,28.18 22.83,28.18 22.47,27.81 22.1,27.81 v1(21.97,27.69)
3DR_TX: length 38.7
  TOP w0.152: v1(21.08,27.69) 21.08,26.92 21.47,26.53 U7.7 ; J3.2 32,10.3 v1(33.02,9.27)
  ART03 w0.127: v1(21.08,27.69) 21.6,28.21 22.36,28.21 22.61,28.45 22.61,28.71 24.04,30.15 28.27,30.15 31.11,27.3 32.51,27.3 32.85,26.97 32.85,21.03 33.4,20.48 33.4,19.7 33.4,19.7 33.4,19.16 33.78,18.78 33.78,10.03 v1(33.02,9.27)
#RST: length 3
  TOP w0.152: U8.13 16.13,15.24 16.26,15.11 16.64,15.11 17.02,14.73 C15.1
$$$7: length 1.9
  TOP w0.152: LED6.2 6.47,7.63 v1(6.35,7.75)
  BOTTOM w0.152: R36.1 6.44,7.84 v1(6.35,7.75)
$$$8: length 3.3
  TOP w0.152: C13.2 28.96,19.68 28.84,19.57 U5.20 26.13,19.57
$$$9: length 13.2
  TOP w0.152: U5.10 21.59,20.07 v1(21.44,19.92)
  ART03 w0.254: v1(26.54,27.81) 24.38,25.65 24.38,24.77 21.59,21.97 21.21,21.97 20.88,21.65 20.88,20.47 v1(21.44,19.92)
  BOTTOM w0.254: v1(26.54,27.81) 27.18,28.45 C7.2
$$$12: length 1.5
  BOTTOM w0.381: U3.4 23.57,4.54 C11.2
$$$13: length 1.8
  TOP w0.152: U13.10 12.7,13.59 12.57,13.72 11.44,13.72 C10.1
$$$14: length 22.1
  TOP w0.152: v1(22.61,6.35) 22.36,6.1 J5.5
  ART03 w0.127: v1(31.95,18.47) 32.27,18.15 32.27,11.32 27.67,6.72 22.97,6.72 v1(22.61,6.35)
  BOTTOM w0.152: v1(31.95,18.47) 31.9,18.41 R4.1
$$$15: length 24.8
  TOP w0.152: J5.6 23.36,6.09 v1(23.62,6.35)
  ART03 w0.127: v1(30.99,21.72) 30.99,21.19 32.16,20.03 32.16,18.83 32.55,18.43 32.55,11.09 27.81,6.35 v1(23.62,6.35)
  BOTTOM w0.152: v1(30.99,21.72) 30.99,21.34 30.61,20.95 R3.1
$$$16: length 26.5
  TOP w0.152: J5.7 24.36,4.42 v1(23.75,3.81)
  ART03 w0.127: v1(23.75,3.81) 25.91,5.97 27.93,5.97 32.87,10.91 32.87,18.51 32.56,18.82 32.56,20.02 31.75,20.83 v1(31.75,21.72)
  BOTTOM w0.152: R2.1 31.24,22.23 v1(31.75,21.72)
$$$17: length 28.4
  TOP w0.152: v1(25.02,3.81) 25.36,4.15 J5.8
  ART03 w0.127: v1(31.88,24.13) 31.5,23.75 31.5,22.86 32.16,22.2 32.16,20.82 32.84,20.13 32.84,18.93 33.15,18.63 33.15,10.79 27.81,5.46 26.67,5.46 v1(25.02,3.81)
  BOTTOM w0.152: v1(31.88,24.13) 31.37,23.62 R1.1
$$$18: length 4
  TOP w0.152: U2.7 12.19,8.76 12.32,8.89 12.32,9.18 12.19,9.31 U2.8 11.14,9.31 11.01,9.44 R12.1 11.01,11.05
$$$19: length 21
  TOP w0.152: J5.4 21.36,6.12 v1(21.59,6.35)
  ART03 w0.127: v1(21.59,6.35) 22.24,7 27.54,7 31.99,11.45 31.99,16.78 v1(31.75,17.02)
  BOTTOM w0.152: R5.1 30.52,17.14 31.62,17.14 v1(31.75,17.02)
$$$20: length 20.6
  TOP w0.152: J5.3 20.36,6.14 v1(20.57,6.35)
  ART03 w0.127: v1(31.62,15.88) 31.24,15.49 31.24,14.73 31.65,14.33 31.65,11.5 27.43,7.28 21.5,7.28 v1(20.57,6.35)
  BOTTOM w0.152: v1(31.62,15.88) 31.5,15.75 R6.1
$$$21: length 19.3
  TOP w0.152: v1(19.56,6.35) 19.36,6.15 J5.2
  ART03 w0.127: v1(31.24,14.19) 31.37,14.06 31.37,11.62 27.31,7.56 20.76,7.56 v1(19.56,6.35)
  BOTTOM w0.152: R7.1 v1(31.24,14.19)
$$$22: length 17.1
  TOP w0.152: J5.1 18.36,6.17 v1(18.54,6.35)
  ART03 w0.127: v1(30.99,11.94) 30.99,11.81 27.01,7.84 19.77,7.84 18.54,6.6 v1(18.54,6.35)
  BOTTOM w0.152: v1(30.99,11.94) 30.86,12.06 R8.1
$$$23: length 16.8
  TOP w0.152: J4.7 4.55,10.57 4.06,11.05 4.06,13.08 v1(3.56,13.59)
  BOTTOM w0.152: v1(3.56,13.59) 4.32,14.35 4.32,19.94 6.29,21.91 6.29,22.29 6.6,22.61 6.6,23.02 7.21,23.62 R39.1
$$$24: length 14
  TOP w0.152: J4.6 5.98,11.57 6.35,11.94 v1(6.35,12.19)
  BOTTOM w0.152: R40.1 7.71,21.46 6.86,21.46 5.21,19.81 5.21,13.34 v1(6.35,12.19)
$$$25: length 9
  TOP w0.152: J4.4 5.82,13.56 v1(6.35,14.1) ; v1(7.73,19.56) 7.86,19.68 R42.1
  BOTTOM w0.152: v1(7.73,19.56) 6.99,19.56 6.1,18.67 6.1,14.35 v1(6.35,14.1)
$$$26: length 3.5
  TOP w0.152: R43.1 8.03,14.86 7.78,14.61 5.12,14.61 J4.3
$$$27: length 3.5
  TOP w0.152: J4.2 7.31,15.56 7.62,15.88 R44.1
$$$29: length 8
  TOP w0.152: v1(10.05,13.93) 10.05,13.32 10.29,13.08 10.92,13.08 11.01,12.99 C8.1 ; U13.8 13.85,14.34 14.22,13.97 v1(14.48,13.97)
  ART03 w0.127: v1(14.48,13.97) 14.34,13.83 10.15,13.83 v1(10.05,13.93)
$$$30: length 1.4
  TOP w0.152: U13.12 12.58,12.58 12.45,12.45 C8.2
$$$31: length 2.2
  TOP w0.152: LED1.2 31.74,26.54 v1(32,26.54)
  BOTTOM w0.152: v1(32,26.54) 31.88,26.54 31.58,26.25 R13.1
$$$32: length 2.2
  TOP w0.152: v1(28.19,26.29) 28.56,25.92 LED2.2
  BOTTOM w0.152: R18.1 28.23,26.25 v1(28.19,26.29)
$$$33: length 2.4
  TOP w0.152: LED3.2 32.27,25.92 v1(32,25.65)
  BOTTOM w0.152: R20.1 32.6,26.25 v1(32,25.65)
$$$34: length 3.2
  BOTTOM w0.254: Y2.1 20.34,8.91 20.59,9.16 21.09,9.16 21.37,9.43 U1.34
$$$35: length 2.7
  BOTTOM w0.254: Y2.2 22.34,8.65 21.87,9.12 U1.33
$$$4718: length 1.7
  TOP w0.152: R11.2 19.87,22.8 20.33,23.26 SJ4.3
$$$21225: length 11.9
  TOP w0.152: U7.6 22.86,27.03 22.99,26.91 22.99,26.42 24.77,24.64 26.42,24.64 26.67,24.38 26.67,23.24 26.54,23.11 26,23.11 25.9,23.22 23.01,23.22 22.69,23.53 R27.2
$$$21228: length 3.2
  TOP w0.152: 24.6,23.88 R30.2 24.6,24.04 24.13,24.51 22.86,24.51 22.34,25.04 U7.10
$$$23578: length 3.2
  TOP w0.152: R23.1 20.69,21.11 20.69,19.74 R22.1 20.99,19.43 21.59,19.43 21.73,19.57 U5.11
$$$25859: length 19.1
  TOP w0.152: R38.1 v1(6.99,24.26) ; J4.8 4.07,9.57 3.17,10.46 3.17,14.1 v1(3.56,14.48)
  BOTTOM w0.152: v1(6.99,24.26) 6.22,23.5 6.22,22.73 5.97,22.48 5.97,22.1 3.81,19.94 3.81,14.73 v1(3.56,14.48)
$$$25863: length 3.6
  TOP w0.152: J4.1 7.87,16.56 8.45,17.14 R45.1
$$$27159: length 9.2
  TOP w0.165: J18.2 10.54,29.99 10.54,30.59 10.83,30.88 11.59,30.88 11.72,30.75 13.32,30.75 15.3,28.77 15.3,28.32 14.95,27.97 Z2.1 15.26,27.66 15.26,26.98 R31.2
$$$27161: length 10.4
  TOP w0.165: J18.3 10.16,29.97 10.16,30.73 10.67,31.24 11.74,31.24 11.87,31.11 13.47,31.11 15.66,28.92 15.66,28.32 Z1.1 15.62,27.57 15.62,26.84 R34.2
$$$27480: length 5.3
  TOP w0.152: U8.2 12.85,20.3 12.12,21.03 11.67,21.03 R29.1 11.34,20.7 10,20.7 9.86,20.84 Y1.2
$$$27485: length 5.8
  TOP w0.152: U8.1 12.85,20.8 12.32,21.34 11.72,21.34 R29.2 10.88,21.63 10.54,21.97 10.54,22.34 10.03,22.84 Y1.1
$$$27841: length 1.7
  TOP w0.152: C17.1 16.51,22.48 16.63,22.36 U8.27
$$$27864: length 4.5
  TOP w0.165: U8.30 15.12,22.23 15.19,22.3 15.19,25.41 R31.1
$$$27865: length 4.5
  TOP w0.165: R34.1 15.56,25.42 15.56,22.3 15.62,22.23 U8.29
$$$30141: length 6
  BOTTOM w0.152: U1.98 24.37,27.16 24.64,27.43 27.43,27.43 28.19,28.19 R28.2
$$$32146: length 2.4
  TOP w0.152: v1(19.05,31.11) 18.85,30.92 J6.10
  BOTTOM w0.152: v1(19.05,31.11) 18.71,30.77 R50.1
$$$32167: length 3
  TOP w0.152: v1(18.16,31.11) 17.85,30.81 J6.11
  BOTTOM w0.152: v1(18.16,31.11) 17.82,31.11 R52.1
$$$32195: length 3.1
  TOP w0.152: v1(16.64,32) 16.85,31.79 J6.12
  BOTTOM w0.152: R53.1 16.93,31.71 v1(16.64,32)
CH5: length 33.3
  TOP w0.152: v1(18.92,22.99) 19.43,22.99 19.78,23.34 SJ4.1 ; J4.5 6.22,12.56 6.35,12.69 v1(6.35,13.21)
  ART03 w0.127: v1(6.99,20.95) 7.37,21.34 7.37,23.24 7.62,23.5 8.26,23.5 9.55,24.79 9.55,26.19 10.03,26.67 11.18,26.67 11.43,26.42 11.43,24.89 12.06,24.26 12.06,22.86 12.57,22.35 13.26,22.35 13.77,22.86 18.8,22.86 v1(18.92,22.99)
  BOTTOM w0.152: R41.1 v1(6.99,20.95) 5.71,19.68 5.71,13.84 v1(6.35,13.21)
CS_DF: length 6.4
  BOTTOM w0.152: IC2.4 4.58,5.71 3.28,7 U_15.4
CS_MS5611: length 2.9
  TOP w0.152: U12.5 25.88,12.72 26.54,12.06 R33.1 R10.1
HI: length 2.3
  BOTTOM w0.152: R14.2 9.56,13.46 10.16,13.46 10.55,13.85 U1.54
IN0: length 9.5
  TOP w0.152: v1(10.03,16.89) 9.78,17.14 R45.2 ; U8.14 v1(16.63,15.62)
  ART03 w0.127: v1(10.03,16.89) 11.94,16.89 12.32,17.27 13.11,17.27 13.64,16.74 15.9,16.74 16.63,16.01 v1(16.63,15.62)
IN4: length 14.3
  TOP w0.152: v1(19.84,17.68) 19.68,17.53 19.02,17.53 18.75,17.8 U8.18
  ART03 w0.127: v1(10.16,21.08) 10.72,20.52 13.64,20.52 14.33,19.84 14.41,19.84 14.8,19.84 14.81,19.84 15.67,19.84 15.68,19.84 16.07,19.84 16.08,19.84 16.94,19.84 16.95,19.84 17.34,19.84 17.35,19.84 17.53,19.84 17.93,19.43 17.93,18.99 18.67,18.26 18.67,17.89 19.02,17.54 19.7,17.54 v1(19.84,17.68)
  BOTTOM w0.152: R41.2 10.03,20.95 v1(10.16,21.08)
IN5: length 13.4
  TOP w0.152: v1(19.18,17.91) 18.78,18.3 U8.19
  ART03 w0.127: v1(19.18,17.91) 19.18,17.91 19.18,18.14 18.24,19.08 18.24,19.99 17.42,20.8 11.46,20.8 v1(10.16,22.1)
  BOTTOM w0.152: R40.2 10.03,22.23 v1(10.16,22.1)
IN6: length 13.9
  TOP w0.152: U8.20 19.04,18.8 v1(19.17,18.67)
  ART03 w0.127: v1(10.16,23.62) 10.16,22.73 11.68,21.21 17.53,21.21 18.52,20.22 18.52,19.33 v1(19.17,18.67)
  BOTTOM w0.152: R39.2 v1(10.16,23.62)
IN7: length 14.3
  TOP w0.152: U8.21 19.05,19.3 v1(19.18,19.43) ; 9.18,24.26 R38.2 9.91,24.26 v1(10.16,24.51)
  ART03 w0.127: v1(10.16,24.51) 10.92,23.75 10.92,22.61 11.94,21.59 17.78,21.59 18.8,20.57 18.8,19.81 v1(19.18,19.43)
INT: length 2.7
  TOP w0.152: R19.1 19.87,18.4 20.54,19.07 U5.12
JP_VCC: length 3.3
  BOTTOM w0.381: R49.1 3.61,28.07 SJ1.2 SJ1.1 5.59,27.94
  vias: v1(6.22,28.7) v1(6.22,27.94) v1(6.99,28.7) v1(6.99,27.94)
LO: length 7.6
  BOTTOM w0.152: U1.56 10.53,14.85 10.41,14.73 10.41,14.48 10.54,14.35 U1.55 12.29,14.35 12.52,14.12 12.52,13.64 12.23,13.35 U1.53 10.65,13.35 10.38,13.08 9.82,13.08 R15.2
MISO_3V3: length 11.2
  TOP w0.152: U5.9 21.4,20.57 v1(21.39,20.58) ; v1(24.26,13.97) 24.26,13.98 U12.6 25.7,13.98 26.04,14.31 U_14.5
  BOTTOM w0.152: v1(24.26,13.97) 22.86,15.37 22.86,17.53 21.84,18.54 21.84,20.12 v1(21.39,20.58)
MOSI_3V3: length 13
  TOP w0.152: v1(24.26,15.49) 24.52,15.23 U12.7 25.91,15.23 26.04,15.11 U_14.3 ; 26.13,21.57 U5.24 26.82,21.57 27.69,20.7 28.41,20.7 v1(28.58,20.87)
  ART03 w0.152: v1(24.26,15.49) 24.51,15.49 28.96,19.94 28.96,20.49 v1(28.58,20.87)
MOSI_DF: length 12.3
  BOTTOM w0.152: IC2.1 9.02,1.91 9.91,2.79 9.91,6.03 9.33,6.6 4.7,6.6 4.08,7.22 U_15.2
NET_R32_2: length 3.2
  TOP w0.152: v1(31.75,17.78) 32.4,17.13 LED4.2
  BOTTOM w0.152: v1(31.75,17.78) 32.04,17.78 R32.2
NET_R35_2: length 2.5
  TOP w0.152: LED5.2 33.05,20.21 33.05,21.01 v1(33.22,21.18)
  BOTTOM w0.152: R35.2 33.02,20.98 v1(33.22,21.18)
NET_R51_2: length 2.6
  TOP w0.152: v1(31.88,23.24) 32.09,23.24 32.59,23.74 LED7.2
  BOTTOM w0.152: v1(31.88,23.24) 32.04,23.41 R51.2
PA1: length 17.2
  TOP w0.152: R47.1 10.54,18.41 10.41,18.29 10.41,16.76 11.05,16.13 12.19,16.13 v1(12.83,15.49)
  BOTTOM w0.152: U1.77 13.87,25.5 14.22,25.15 14.22,23.37 13.08,22.23 13.08,21.34 13.08,21.12 13.67,20.54 13.67,16.33 13.64,16.31 v1(12.83,15.49)
PA2: length 13.7
  TOP w0.152: v1(12.83,16.26) 12.57,16.51 11.18,16.51 11.01,16.68 R46.1
  BOTTOM w0.152: v1(12.83,16.26) 13.36,16.79 13.36,20.24 12.78,20.83 12.78,21.08 12.78,22.35 13.92,23.49 13.92,23.83 13.92,24.91 13.37,25.46 U1.76
PA3: length 27.5
  TOP w0.152: v1(32,27.69) 32.27,27.42 LED3.1
  ART03 w0.127: v1(32,27.69) 31.36,27.69 28.56,30.48 23.75,30.48 22.21,28.94 17.89,28.94 14.61,25.65 12.4,25.65 v1(11.96,26.09)
  BOTTOM w0.152: v1(11.96,26.09) 12.62,25.43 12.62,24.79 12.18,24.35 U1.75
PA4: length 26.8
  TOP w0.152: v1(30.92,28.64) 29.71,27.42 LED2.1
  ART03 w0.127: v1(12.62,26.09) 14.4,26.09 17.65,29.34 22.1,29.34 23.52,30.76 28.8,30.76 v1(30.92,28.64)
  BOTTOM w0.152: v1(12.62,26.09) 12.95,25.76 12.95,24.66 12.14,23.85 U1.74
PA5: length 36.7
  TOP w0.152: LED1.1 31.11,27.94 31.75,28.57 v1(32,28.57)
  ART03 w0.127: v1(32,28.57) 31.75,28.57 29.26,31.06 23.32,31.06 22.1,29.84 17.4,29.84 14.73,27.18 10.03,27.18 9.14,26.29 9.14,25.02 8.13,24 7.65,24 6.99,23.34 v1(6.99,22.86)
  BOTTOM w0.152: U1.73 10.52,23.35 10.21,23.04 7.16,23.04 v1(6.99,22.86)
PA6: length 22.6
  BOTTOM w0.152: U1.72 10.53,22.85 10.41,22.73 7.75,22.73 7.37,22.35 6.83,22.35 6.6,22.13 6.6,21.72 4.7,19.81 4.7,13.08 5.97,11.81 6.48,11.81 6.73,11.56 6.73,11.15 6.51,10.92 4.06,10.92 3.28,10.14 U_15.8
PB0: length 2.6
  TOP w0.152: U_14.8 28.81,14.71 v1(28.83,14.73)
  BOTTOM w0.152: v1(28.83,14.73) 28.21,15.35 U1.19
PB1: length 5.3
  TOP w0.152: R21.1 v1(28.83,15.79) 28.56,15.51 U_14.10
  BOTTOM w0.152: v1(28.83,15.79) 28.83,15.44 29.34,14.94 29.34,14.7 28.99,14.35 28.63,14.35 28.13,14.85 U1.20
PB2: length 4.9
  TOP w0.152: v1(29.46,14.22) 29.59,14.35 R21.2 29.26,15.28 28.87,15.28 28.7,15.11 U_14.9
  BOTTOM w0.152: v1(29.46,14.22) 29.26,14.02 28.52,14.02 28.19,14.35 U1.21
PB3: length 6.8
  TOP w0.152: R17.1 30.61,14.44 v1(30.35,14.19) 29.96,13.79 29.1,13.79 28.57,14.31 U_14.7
  BOTTOM w0.152: v1(30.35,14.19) 29.88,13.72 28.32,13.72 28.19,13.85 U1.22
PB5: length 2.2
  BOTTOM w0.152: R7.2 29.21,13.21 28.85,12.85 U1.24
PB6: length 2.2
  BOTTOM w0.152: R8.2 29.14,12.35 U1.25
PB7: length 36.9
  ART03 w0.127: v1(24.49,11.58) 25.04,11.58 27.05,13.59 27.05,15.88 30.61,19.43 30.61,26.67 27.69,29.59 24.89,29.59 24,28.7 24,27.95 23.35,27.3 20.85,27.3 19.96,28.19 19.43,28.19 v1(19.05,28.57)
  BOTTOM w0.152: v1(24.49,11.58) 24.59,11.68 25.15,11.68 25.36,11.47 U1.26 ; v1(19.05,28.57) 17.87,29.76 R50.2
PC4: length 2.4
  BOTTOM w0.152: R48.1 9.81,14.61 10.55,15.35 U1.57
PC6: length 6.9
  TOP w0.152: v1(14.48,12.7) 14.86,12.32 U13.15
  BOTTOM w0.152: U1.59 12.1,16.35 12.4,16.05 12.4,15.34 12.62,15.11 12.95,15.11 13.34,14.73 13.34,13.21 13.84,12.7 v1(14.48,12.7)
PC7_LED: length 23.3
  TOP w0.152: LED7.1 31.74,22.24 31.11,22.86 30.35,22.86 29.26,23.95 v1(28.68,23.95) ; U8.22 18.78,19.8 v1(19.18,20.19)
  ART03 w0.127: v1(28.68,23.95) 28.7,23.98 28.7,26.84 27.34,28.19 25.65,28.19 25.64,28.18 25.63,28.18 23.38,25.93 23.38,25.03 19.18,20.83 v1(19.18,20.19)
PD0: length 10.9
  TOP w0.152: v1(17.53,11.68) 17.14,12.06 16.26,12.06 15.24,11.05 13.21,11.05 12.57,10.41 12.42,10.41 12.19,10.19 12.19,9.74 12.7,9.23 12.7,8.76 12.2,8.26 U2.6
  BOTTOM w0.152: v1(17.53,11.68) 17.27,11.68 16.87,11.28 U1.43
PD1: length 9
  TOP w0.152: v1(16.64,11.68) 15.49,10.54 13.34,10.54 13.08,10.29 13.08,8.64 12.15,7.71 U2.5
  BOTTOM w0.152: v1(16.64,11.68) 16.37,11.41 U1.44
PD2: length 9.7
  TOP w0.152: J2.5 12.29,5.94 12.57,6.22 13.97,6.22 14.1,6.1 16.05,6.1 v1(16.79,6.84)
  BOTTOM w0.152: v1(16.79,6.84) 16.76,6.86 16.76,8.5 15.87,9.4 U1.45
PD3: length 10.1
  TOP w0.152: v1(16,6.86) 15.58,6.44 14.43,6.44 14.27,6.6 11.68,6.6 11.29,6.21 J2.4
  BOTTOM w0.152: v1(16,6.86) 16.13,6.99 16.13,8.64 15.37,9.4 U1.46
PE0: length 2.2
  TOP w0.152: v1(26.16,24.26) 25.91,24 25.44,24 R30.1
  BOTTOM w0.152: U1.2 26.57,23.85 v1(26.16,24.26)
PE1: length 4.1
  TOP w0.152: R27.1 24.02,23.52 26.14,23.52 v1(26.16,23.5)
  BOTTOM w0.152: U1.3 26.31,23.35 v1(26.16,23.5)
PE3: length 2.8
  BOTTOM w0.152: U1.5 28.19,22.35 28.57,22.73 28.57,23.11 29.08,23.62 R1.2
PE4: length 2.2
  BOTTOM w0.152: R2.2 28.5,22.23 28.12,21.85 U1.6
PE5: length 2.2
  BOTTOM w0.152: U1.7 28.31,21.35 28.41,21.25 29.13,21.25 R3.2
PE6: length 11.6
  TOP w0.152: R19.2 20.71,17.69 v1(20.7,17.68)
  BOTTOM w0.152: U1.8 26.01,20.85 24.89,21.97 21.46,21.97 20.94,21.44 20.94,17.91 v1(20.7,17.68)
PF0: length 6.4
  TOP w0.152: v1(25.78,27.81) 26.16,28.19 27.05,28.19 27.85,28.99 J6.1
  BOTTOM w0.152: U1.97 23.87,27.16 24.51,27.81 v1(25.78,27.81)
PF1: length 6
  TOP w0.152: J6.2 26.85,28.86 26.54,28.55 v1(26.54,28.57)
  BOTTOM w0.152: U1.96 23.37,27.18 24.38,28.19 26.16,28.19 v1(26.54,28.57)
PF2: length 5.5
  TOP w0.152: J6.3 25.85,28.77 v1(25.65,28.57)
  BOTTOM w0.152: v1(25.65,28.57) 24.33,28.57 22.87,27.11 U1.95
PF3: length 5.1
  TOP w0.152: J6.4 24.85,28.66 24.38,28.19 23.37,28.19 v1(22.99,27.81)
  BOTTOM w0.152: v1(22.99,27.81) 22.99,27.69 22.37,27.06 U1.94
PF4: length 4.8
  TOP w0.152: v1(22.99,28.57) 23.72,28.57 23.85,28.7 J6.5
  BOTTOM w0.152: U1.93 21.87,27.06 22.13,27.33 22.2,27.33 22.48,27.61 22.48,28.07 v1(22.99,28.57)
PF5: length 4.4
  TOP w0.152: J6.6 22.85,28.98 22.45,28.57 v1(21.97,28.57)
  BOTTOM w0.152: U1.92 21.37,27.21 21.46,27.3 21.46,28.07 v1(21.97,28.57)
PF6: length 4.4
  TOP w0.152: v1(21.08,28.57) 21.43,28.57 21.85,28.99 J6.7
  BOTTOM w0.152: v1(21.08,28.57) 20.57,28.07 20.57,27.51 20.87,27.22 U1.91
PF7: length 4
  TOP w0.152: J6.8 20.85,28.88 20.32,28.35 20.32,28.07 v1(19.94,27.69)
  BOTTOM w0.152: U1.90 20.37,27.1 19.94,27.53 v1(19.94,27.69)
PG0: length 12.4
  TOP w0.152: v1(6.35,11.3) 6.86,11.81 6.86,13.21 7.24,13.59 9.14,13.59 v1(10.03,12.7)
  BOTTOM w0.152: U1.51 10.38,12.35 v1(10.03,12.7) ; v1(6.35,11.3) 6.22,11.43 3.81,11.43 2.88,10.5 U_15.7
PG1: length 22.6
  TOP w0.152: R10.2 28.45,13.08 v1(28.7,13.34)
  ART03 w0.127: v1(11.56,11.68) 11.68,11.81 12.57,11.81 12.83,11.56 15.37,11.56 16.51,10.41 23.78,10.41 24.44,11.07 26.44,11.07 v1(28.7,13.34)
  BOTTOM w0.152: v1(11.56,11.68) 11.91,11.68 12.34,12.12 12.34,12.68 12.17,12.85 U1.52
PH3: length 2.5
  BOTTOM w0.152: R4.2 28.36,17.35 U1.15
PH4: length 2.4
  BOTTOM w0.152: U1.16 28.53,16.85 28.96,17.27 R5.2
PH5: length 2.4
  BOTTOM w0.152: U1.17 28.95,16.35 R6.2
PJ0: length 23.3
  BOTTOM w0.152: U1.63 8.32,18.35 7.37,17.4 7.37,12.82 8.88,11.3 9.65,11.3 10.86,10.1 10.86,7.3 11.81,6.35 11.81,3.05 12.95,1.91 IC2.8
PJ1: length 16.4
  BOTTOM w0.152: U1.64 11.36,18.85 7.64,18.85 7.04,18.24 7.04,12.4 7.42,12.01 7.42,10.92 6.78,10.29 4.45,10.29 4.08,9.92 U_15.10
PJ2: length 17.2
  BOTTOM w0.152: U1.65 10.49,19.35 10.32,19.18 7.37,19.18 6.6,18.41 6.6,14.61 6.73,14.48 6.73,12.06 7.04,11.76 7.04,11.43 7.04,11.02 6.63,10.62 4.27,10.62 3.68,10.03 U_15.9
PJ3: length 15.7
  TOP w0.152: v1(19.9,19) R22.2
  ART03 w0.127: v1(10.16,20.32) 10.24,20.24 10.6,20.24 11.29,19.56 14.29,19.56 15.56,19.56 16.83,19.56 17.4,19.56 17.65,19.3 17.65,18.81 18.39,18.07 18.39,18.01 18.39,17.57 18.7,17.26 19.94,17.26 20.21,17.53 20.21,18.7 v1(19.9,19)
  BOTTOM w0.152: v1(10.16,20.32) 10.63,19.85 U1.66
PK0: length 3.8
  TOP w0.152: J6.9 19.85,28.66 v1(19.94,28.57)
  BOTTOM w0.152: v1(19.94,28.57) 19.56,28.19 19.56,27.43 19.87,27.12 U1.89
PK4: length 16.5
  TOP w0.152: v1(6.99,27.05) 6.3,26.37 6.3,25.48 6.09,25.26 J1.3
  BOTTOM w0.152: U1.85 17.87,27.35 17.45,27.76 16.94,27.76 15.75,28.96 13.34,28.96 12.19,27.81 9.65,27.81 8.89,27.05 v1(6.99,27.05)
PK5: length 16.2
  TOP w0.152: v1(6.99,26.29) 6.6,25.91 6.6,24.64 6.23,24.27 J1.4
  BOTTOM w0.152: U1.84 17.37,27.21 17.12,27.46 16.82,27.46 15.7,28.57 13.59,28.57 12.4,27.38 9.86,27.38 9.14,26.67 7.37,26.67 v1(6.99,26.29)
PL1: length 16.8
  TOP w0.152: v1(20.69,22.99) 20.71,22.96 R11.1
  BOTTOM w0.152: U1.36 20.37,14.14 21.46,15.24 21.46,16.89 21.08,17.27 19.18,17.27 18.8,17.65 18.8,18.51 18.79,18.51 18.79,18.83 18.8,18.83 18.8,20.7 19.68,21.59 19.68,21.98 v1(20.69,22.99)
PL4: length 41.6
  ART03 w0.127: v1(19.68,11.56) 20.07,11.18 22.48,11.18 24,12.7 24.54,12.7 25.02,13.18 25.02,15.24 28.33,18.55 28.73,18.55 29.72,19.55 29.72,26.42 27.18,28.96 25.4,28.96 24.77,28.32 24.77,27.81 23.56,26.61 19.62,26.61 18.8,27.43 18.8,27.94 v1(18.16,28.57)
  BOTTOM w0.152: v1(18.16,28.57) 17.14,28.57 16.09,29.63 R52.2 ; U1.39 18.87,11.12 19.3,11.56 v1(19.68,11.56)
PL5: length 45.1
  ART03 w0.127: v1(19.18,27.69) 19.91,26.95 23.39,26.95 24.38,27.94 24.38,28.45 25.17,29.24 27.41,29.24 30.23,26.42 30.23,19.56 25.78,15.11 25.78,13.21 24.64,12.06 24.26,12.06 24,11.81 24,11.43 23.37,10.79 19.43,10.79 v1(18.67,11.56)
  BOTTOM w0.152: v1(18.67,11.56) 18.37,11.25 U1.40 ; v1(19.18,27.69) 18.8,28.07 17.14,28.07 15.49,29.72 15.49,30.65 R53.2
PPM_MISO: length 12.3
  TOP w0.152: U8.17 18.81,17.3 19.1,17.02 v1(19.1,16.89) ; R42.2 10.03,19.68 v1(10.16,19.56)
  ART03 w0.127: v1(19.1,16.89) 18.67,16.89 18.03,17.53 18.03,18.03 17.5,18.57 17.39,18.57 14.33,18.57 14.11,18.78 10.93,18.78 v1(10.16,19.56)
PPM_MOSI: length 14.7
  TOP w0.152: R43.2 9.91,14.86 10.03,14.99 v1(10.03,15.37) ; v1(18.16,15.62) 17.63,16.16 U8.16
  ART03 w0.127: v1(18.16,15.62) 18.16,15.99 17.37,16.78 17.37,16.79 16.87,17.3 14.07,17.3 13.46,17.91 10.92,17.91 10.55,17.54 10,17.54 9.76,17.54 9.3,17.07 9.3,16.1 v1(10.03,15.37)
PPM_OUT: length 6.5
  TOP w0.152: SJ4.2 20.88,23.44 21.34,22.99 21.34,21.97 21.08,21.72 19.59,21.72 19.18,21.31 19.18,20.73 18.75,20.3 U8.23
  TOP w0.203: SJ4.2 20.42,23.77
PPM_PC2: length 30.4
  TOP w0.152: U8.5 12.95,18.8 12.95,18.8 v1(12.57,18.41) ; U7.1 25.51,25.04 25.4,25.15 25.4,26.8 25.64,27.03 U7.5 26.43,27.03 v1(27.2,27.81)
  ART03 w0.127: v1(27.2,27.81) 25.65,26.26 25.65,25.4 21.82,21.56 21.82,19.79 21.81,19.77 21.81,19.76 21.59,19.55 21.58,19.55 21.18,19.15 21.18,16.23 20.57,15.62 19.18,15.62 17.65,17.14 17.65,17.95 17.32,18.29 14.1,18.29 13.97,18.41 v1(12.57,18.41)
PPM_PD0: length 2
  TOP w0.152: U8.6 13.09,18.3 12.7,17.91 12.36,17.91 R47.2
PPM_PD1: length 1.9
  TOP w0.152: U8.7 13.02,17.8 12.83,17.6 12.31,17.6 R46.2
PPM_RST: length 15.8
  TOP w0.152: U8.24 18.64,20.8 18.8,20.95 18.8,21.46 v1(19.18,21.84)
  ART03 w0.127: v1(19.18,21.84) 19.05,21.97 12.32,21.97 11.56,22.73 11.56,23.75 10.16,25.15 v1(10.16,26.16)
  BOTTOM w0.152: v1(10.16,26.16) 10.03,26.04 R54.1 R37.1
PPM_RX: length 25.8
  TOP w0.152: U7.4 26.69,26.53 27.19,27.04 v1(27.19,27.04) ; U8.8 12.98,17.3 v1(12.57,16.89)
  ART03 w0.127: v1(27.19,27.04) 26.42,26.26 26.42,25.53 22.1,21.21 22.1,19.43 21.59,18.92 21.59,16 20.84,15.25 16.24,15.25 16,15.49 16,16 15.62,16.38 13.59,16.38 13.08,16.89 v1(12.57,16.89)
PPM_SCK: length 12.1
  TOP w0.152: U8.15 17.13,15.91 v1(17.41,15.63) ; v1(10.03,16.13) 9.78,15.88 R44.2
  ART03 w0.127: v1(17.41,15.63) 17.4,15.63 17.4,15.99 16.37,17.02 13.84,17.02 13.23,17.63 11.91,17.63 11.54,17.26 9.88,17.26 9.66,17.04 9.66,16.5 v1(10.03,16.13)
PPM_TX: length 24.3
  TOP w0.152: U7.2 27.18,25.54 v1(27.19,25.53) ; U8.9 14.12,16.16 v1(13.59,15.62)
  ART03 w0.127: v1(27.19,25.53) 26.91,25.53 22.42,21.03 22.42,19.24 21.97,18.8 21.97,15.75 21.08,14.86 16.78,14.86 16.66,14.97 16.36,14.97 16.33,14.95 16.04,14.95 15.62,15.37 15.62,15.75 15.38,15.99 14.97,15.99 14.76,15.77 14.76,15.77 14.72,15.74 14.72,15.47 14.5,15.25 13.96,15.25 v1(13.59,15.62)
RST: length 21.9
  TOP w0.152: SW1.3 16.22,9.82 16.51,9.53 16.51,8.76 16.76,8.51 17.27,8.51 v1(17.78,9.02) 18.58,9.82 SW1.4 19.98,9.82 20.95,10.79 v1(20.95,11.56) 21.37,11.98 D2.1 D3.2 21.37,14.95 21.25,15.08 18.67,15.08 C15.2 R26.1
  BOTTOM w0.152: v1(17.78,9.02) 18,8.8 R24.1 ; v1(20.95,11.56) 21.59,11.56 22.01,11.98 22.57,11.98 23.37,11.18 U1.30
RST_DF: length 7.6
  BOTTOM w0.152: IC2.3 7.14,4.44 6.25,5.33 4.19,5.33 2.88,6.64 U_15.5
RXLED: length 63
  TOP w0.152: LED4.1 34.15,15.63 v1(34.16,15.62) ; v1(14.35,15.62) 14.62,15.89 U8.10
  ART03 w0.127: v1(14.35,15.62) 13.98,15.99 13.19,15.99 13.08,15.88 11.68,15.88 10.81,15 9.77,15 9.02,15.75 9.02,17.19 9.53,17.69 9.53,19.06 8.37,20.22 7.09,20.22 6.6,20.7 6.6,23.36 7.76,24.51 8,24.51 8.76,25.27 8.76,26.42 9.91,27.56 14.48,27.56 17.27,30.35 21.97,30.35 22.96,31.34 29.49,31.34 31.89,28.94 32.16,28.94 33.4,27.7 33.4,21.59 33.68,21.31 33.68,20.59 33.68,20.59 33.68,19.58 33.68,19.28 34.16,18.8 v1(34.16,15.62)
SCK_3V3: length 11.8
  TOP w0.152: v1(24.26,16.26) 24.49,16.49 U12.8 25.55,16.49 25.78,16.26 25.78,15.88 26.14,15.51 U_14.2 ; 26.13,21.07 U5.23 26.81,21.07 27.48,20.4 28.37,20.4 v1(28.56,20.21)
  ART03 w0.152: v1(28.56,20.21) 24.61,16.26 v1(24.26,16.26)
SCK_DF: length 10.8
  BOTTOM w0.152: U_15.3 3.68,7.06 4.5,6.24 9.12,6.24 9.4,5.97 9.4,3.43 9.15,3.18 IC2.2
SCL1: length 36.3
  TOP w0.152: U13.1 16.65,12.58 v1(16.77,12.7) ; v1(29.34,22.89) 29.43,22.8 R9.1 ; J2.1 8.3,6.18 8,6.48 8,8.51 8.25,8.76 v1(9.78,8.76)
  ART03 w0.127: v1(29.34,22.89) 29.34,21.84 28.83,21.34 28.45,21.34 23.5,16.38 23.5,13.59 22.1,12.19 17.27,12.19 v1(16.77,12.7) 16.13,12.7 15.37,11.94 13.84,11.94 13.59,12.19 11.43,12.19 10.92,11.68 10.92,9.9 v1(9.78,8.76)
SDA1: length 39
  TOP w0.152: v1(15.24,12.7) 15.36,12.58 U13.16 ; v1(9.78,7.75) 9.27,8.26 8.38,8.26 8.31,8.18 8.31,7.06 9.3,6.07 J2.2
  TOP w0.203: SJ10.1 SJ10.2 28.26,22.03 v1(28.57,21.72) 29.21,21.72 29.43,21.5 R16.1
  ART03 w0.127: v1(9.78,7.75) 9.27,8.26 9.27,9.02 9.68,9.42 9.98,9.42 10.54,9.98 10.54,11.81 11.3,12.57 13.6,12.57 13.86,12.32 14.86,12.32 v1(15.24,12.7) 15.61,13.07 17.03,13.07 17.4,12.7 21.97,12.7 22.86,13.59 22.86,16.51 28.07,21.72 v1(28.57,21.72)
SPI_OE: length 40.1
  TOP w0.152: v1(7.8,11.77) 9.54,11.77 v1(9.58,11.81) 9.65,11.73 9.65,11.3 9.4,11.05 R25.2 ; v1(16.89,9.02) 16.89,9.49 18.07,10.67 18.8,10.67 19.3,11.18 19.3,12.03 D2.2 20.74,13.46 v1(20.83,13.46) ; U_14.12 27.3,16.38 26.24,17.45 24.13,17.45 23.7,17.02 23.67,17.02 23.67,17.02 22.73,17.02 v1(22.48,17.27)
  BOTTOM w0.152: v1(7.8,11.77) 7.8,10.09 6.85,9.14 5.84,9.14 5.33,8.64 U_15.12 ; v1(22.48,17.27) 22.1,16.89 22.1,14.73 v1(20.83,13.46) ; v1(9.58,11.81) 10.03,11.81 11.35,10.49 11.35,7.61 12.11,6.86 13.84,6.86 14.35,7.37 14.96,7.37 15.97,6.35 17.02,6.35 17.27,6.6 17.27,8.64 v1(16.89,9.02)
SS_3V3: length 11.2
  TOP w0.152: U_14.4 26.02,14.71 25.91,14.61 24.38,14.61 v1(24.26,14.73) ; U5.8 21.68,21.07 v1(21.41,21.34)
  BOTTOM w0.152: v1(21.41,21.34) 22.35,20.4 22.35,18.67 23.4,17.62 23.4,15.59 v1(24.26,14.73)
TXLED: length 62.3
  TOP w0.152: v1(34.05,19.43) 34.05,19.09 33.64,18.68 LED5.1 ; U8.11 v1(15.12,15.62)
  ART03 w0.127: v1(34.05,19.43) 34.05,27.55 32.26,29.34 32,29.34 29.72,31.62 22.73,31.62 21.86,30.75 17.03,30.75 14.22,27.94 9.65,27.94 8.26,26.54 8.26,25.4 7.62,24.77 6.86,24.77 6.22,24.13 6.22,20.57 6.86,19.94 8.26,19.94 9.14,19.05 9.14,17.79 8.64,17.29 8.64,15.61 9.52,14.72 12.05,14.72 12.45,15.11 13.7,15.11 13.87,14.95 14.82,14.95 15.12,15.25 v1(15.12,15.62)
